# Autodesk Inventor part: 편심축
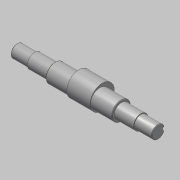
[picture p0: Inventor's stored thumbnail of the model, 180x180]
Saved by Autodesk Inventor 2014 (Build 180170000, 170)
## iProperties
Created: 2015-10
Part Number: 편심축
Document SubType Name: Modeling
Designer: mdu
Density: 7.86 g/cm^3
Material: 강철, 연강
Mass: 1327.93 g
Surface Area: 248.524 cm^2
Volume: 168.948 cm^3
Appearance: 강철
Author: mdu
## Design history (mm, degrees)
sketch "스케치1"
  geometry: L1 (-20.5, -41.331)-(-20.5, 32.669) reference; L2 (7.5, -30.031)-(7.5, 21.369) reference; L3 (135.5, -30.331)-(135.5, 21.669) reference; L4 (121.5, 21.369)-(121.5, -30.031) reference; L5 (184.5, -4.331)-(-57.5, -4.331); L6 (184.5, -4.331)-(184.5, 6.669); L7 (154.5, 8.169)-(121.5, 8.169); L8 (121.5, 8.169)-(121.5, 11.669); L9 (121.5, 11.669)-(7.5, 11.669); L10 (7.5, 11.669)-(7.5, 8.169); L11 (7.5, 8.169)-(-27.5, 8.169); L12 (-27.5, 8.169)-(-27.5, 6.669); L13 (-27.5, 6.669)-(-57.5, 6.669); L14 (-57.5, 6.669)-(-57.5, -4.331); L15 (154.5, 8.169)-(154.5, 6.669); L16 (154.5, 6.669)-(184.5, 6.669); C1 r 32.5 at (64.5, -4.331) reference; 1 further point
  constraints: 24 end point, 8 perpendicular, 5 point on line, 3 parallel, 2 collinear
  dimensions: "d1" = 25 diameter of L11 L5; "d2" = 32 diameter of L9 L5; "d3" = 22 diameter of L13 L5; "d4" = 35 distance of L10.end L11.end; "d5" = 30 distance of L12.end L13.end; "d15" = 33 distance of L7.start L7.end; "d26" = 30 distance of L15.end L6.end
revolve "회전1" sketch "스케치1" stored, may be unused: angle "d6" = 90 deg
node "작업 평면1"
sketch "스케치2"
  geometry: C1 r 16 at (0, 0) reference; C2 r 20.75 at (0, 4)
  constraints: 1 centre point, 1 vertical alignment
  dimensions: "d34" = 4 distance of C2.centre C1.centre; "d35" = 41.5 diameter of C2
extrude "돌출1" join sketch "스케치2" stored distance "d9" = 40; taper "d10" = 0 deg
chamfer "모따기1" distance "d11" = 1; stored, may be unused: second distance "d12" = 2, angle "d13" = 45 deg
node "작업 평면2"
sketch "스케치3"
  geometry: L1 (-15, -10)-(-15, 10) reference; L2 (-15, 3)-(0, 3); L3 (0, -3)-(-15, -3); A1 r 3 centre (0, 0) between (0, -3) and (0, 3); 2 further points
  constraints: 4 end point, 2 perpendicular, 2 point on circle, 2 point on line, 2 tangent, 1 centre point, 1 horizontal alignment, 1 midpoint
  dimensions: "d16" = 18 dimension on A1 L1; "d17" = 6 distance between parallel lines of L3 L2
extrude "돌출2" cut sketch "스케치3" distance "d18" = 3.5; taper "d19" = 0 deg
node "작업 평면3"
node "솔리드1"
mirror "대칭1"
node "참조1"
node "참조2"
node "참조3"
node "참조4"
node "참조5"
other parameters: "d30" = 35
